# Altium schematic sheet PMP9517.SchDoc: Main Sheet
size 431 x 279 mm; Date: Not shown in title block; ApprovedBy: Not shown in title block; CheckedBy: Not shown in title block; Author: Not shown in title block; CompanyName: Not shown in title block; DrawnBy: Brian Gaynor; Engineer: Not shown in title block; Organization: Not shown in title block; Address1: Not shown in title block; Address2: Not shown in title block; Address3: Not shown in title block; Address4: Not shown in title block; DocumentNumber: 1; Revision: Use project parameter SCH_Rev; SheetNumber: 1; SheetTotal: 2; PageSetup: Record=PageOptions|CenterHorizontal=True|CenterVertical=True|PrintScale=0.66|XCorrection=1.00|YCorrection=1.00|PrintKind=0|BorderSize=5000000|LeftOffset=0|BottomOffset=0|Orientation=2|PaperLength=1000|PaperWidth=1000|Scale=100|PaperSource=15|PrintQuality=600|MediaType=1|DitherType=10|PaperKind=Letter|PrintScaleMode=1
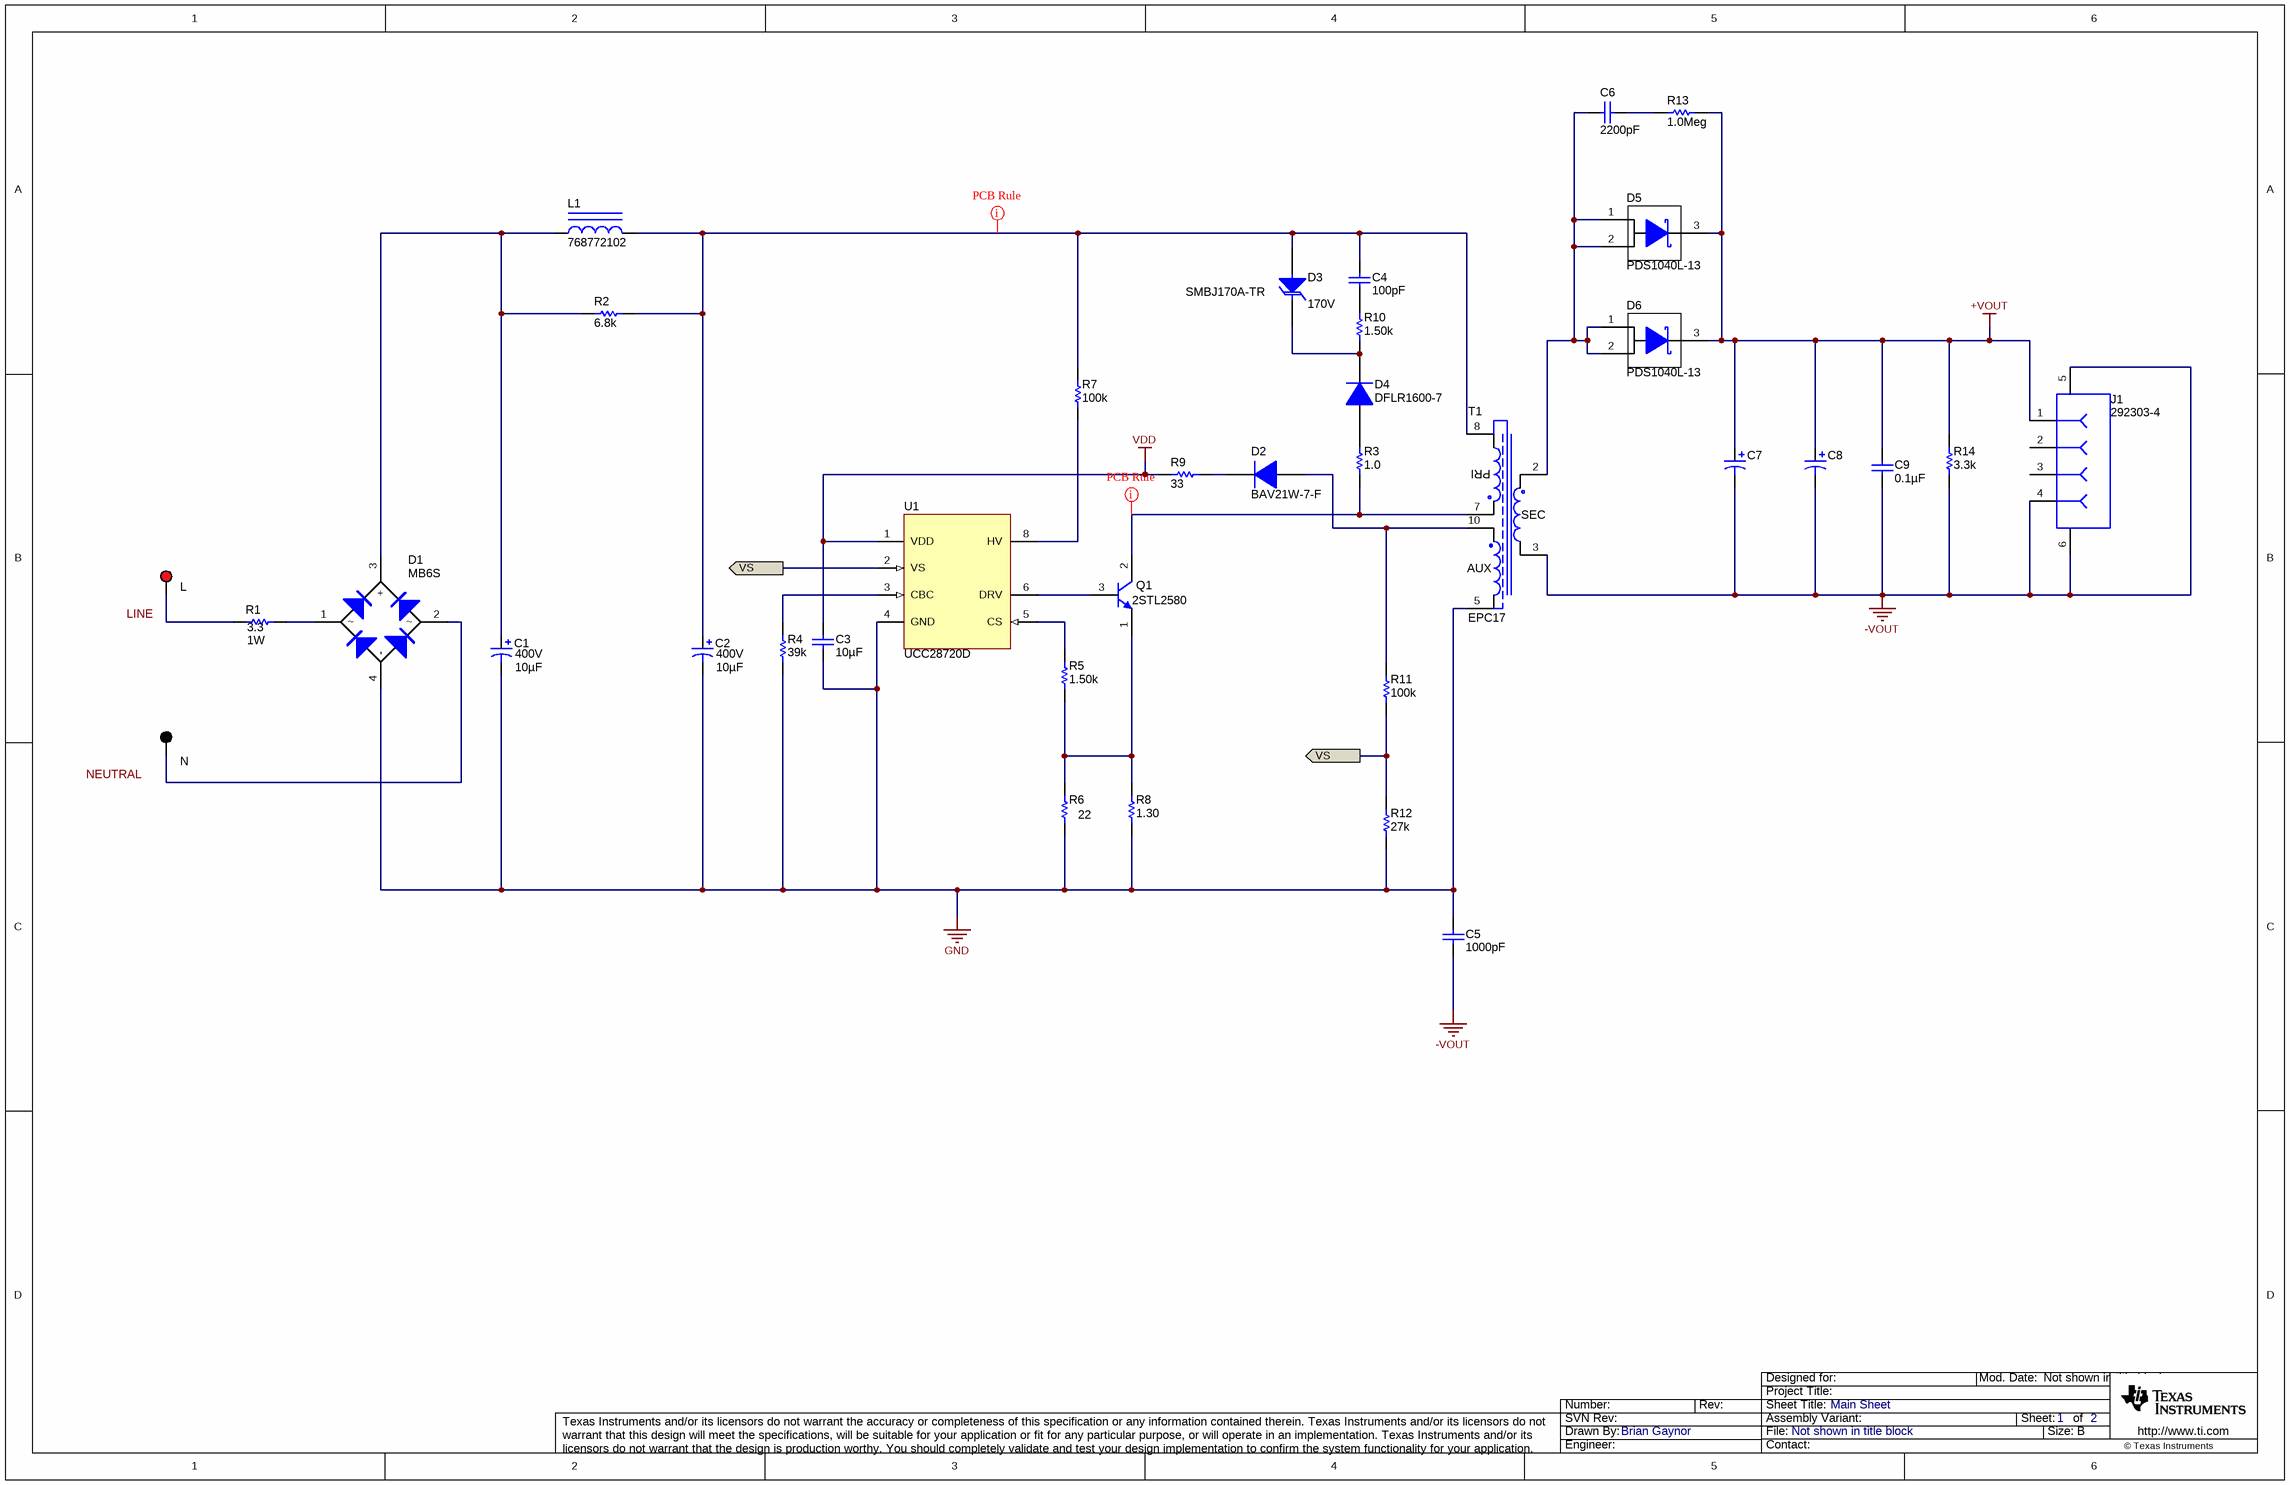
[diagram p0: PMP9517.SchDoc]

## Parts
C1  value 10µF  VDC_V: 400V  [CAPPRD500W60D1000H1250]  (hidden comment: UVC2G100MPD)
C2  value 10µF  VDC_V: 400V  [CAPPRD500W60D1000H1250]  (hidden comment: UVC2G100MPD)
C3  ValueDisplayed: 10µF  [1210]  (hidden comment: 1210YD106KAT2A)
C4  ValueDisplayed: 100pF  [1206]  (hidden comment: C1206C101JCGACTU)
C5  ValueDisplayed: 1000pF  [CAPRD750W60D750H1050]  (hidden comment: VY2102M29Y5UG63V7)
C6  ValueDisplayed: 2200pF  [0805_HV]  (hidden comment: 08055C222KAT2A)
C7  RNE0J122MDN1PX  [NRE-AX_800x1080]  (value not drawn)
C8  CAP ALUM 1200UF 6.3V 20% RADIAL  [NRE-AX_800x1080]  (value not drawn)
C9  ValueDisplayed: 0.1µF  [0805_HV]  (hidden comment: 08055C104JAT2A)
D1  MB6S  [MiniDIP-MB6S]
D2  BAV21W-7-F  [SOD-123]
D3  SMBJ170A-TR  value 170V  [SMB]
D4  DFLR1600-7  [powerDI123]
D5  PDS1040L-13  [powerdi5]
D6  PDS1040L-13  [powerdi5]
J1  292303-4  [CONN_TE_292303-4]
L  5005  [Keystone5005]  (value not drawn)
L1  768772102  [IND_WE-TI_8095]
N  5006  [Keystone5006]  (value not drawn)
Q1  2STL2580  [TO-92_AllBent]
R1  value 3.3  Power_W: 1W  [RES_ERG1S_V]  (hidden comment: SPP1UL3R30JLF)
R2  value 6.8k  [0805_HV]  (hidden comment: CRCW08056K80JNEA)
R3  value 1.0  [1206]  (hidden comment: CRCW12061R00JNEA)
R4  value 39k  [0603]  (hidden comment: CRCW060339K0JNEA)
R5  value 1.50k  [0603]  (hidden comment: CRCW06031K50FKEA)
R6  value 22  [2512M]  (hidden comment: CRCW251222R0JNEGHP)
R7  value 100k  [1206]  (hidden comment: RC1206FR-07100KL)
R8  value 1.30  [2512M]  (hidden comment: ERJ-1TRQF1R3U)
R9  value 33  [0603]  (hidden comment: CRCW060333R0JNEA)
R10  value 1.50k  [1206]  (hidden comment: CRCW12061K50FKEA)
R11  value 100k  [0603]  (hidden comment: CRCW0603100KFKEA)
R12  value 27k  [0603]  (hidden comment: RC0603JR-0727KL)
R13  value 1.0Meg  [0805_HV]  (hidden comment: CRCW08051M00JNEA)
R14  value 3.3k  [0805_HV]  (hidden comment: CRCW08053K30JNEA)
T1  EPC17  [MAG\TH\EPC17]
U1  UCC28720D  [D0007A_N]

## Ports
VS

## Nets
+VOUT: C7.1(+) C8.1(+) C9.2 D5.3(K) D6.3(K) J1.1 R13.2 R14.2
-VOUT: C5.2 C7.2(-) C8.2(-) C9.1 J1.4 J1.5 J1.6 R14.1 T1.3
GND: C1.2(-) C2.2(-) C3.2 C5.1 D1.4(-) R4.1 R6.1 R8.1 R12.1 T1.5 U1.4(GND)
VDD: C3.1 R9.1 U1.1(VDD)
VS: R11.1 R12.2 U1.2(VS) ; port VS
NetC1_1: C1.1(+) D1.3(+) L1.1 R2.1
NetC2_1: C2.1(+) C4.1 D3.2(A) L1.2 R2.2 R7.1 T1.8
NetC4_2: C4.2 R10.2
NetC6_1: C6.1 D5.1(A) D5.2(A) D6.1(A) D6.2(A) T1.2
NetC6_2: C6.2 R13.1
NetD1_1: D1.1 R1.2
NetD1_2: D1.2 N.1
NetD2_1: D2.1(K) R9.2
NetD2_2: D2.2(A) R11.2 T1.10
NetD3_1: D3.1(K) D4.1(K) R10.1
NetD4_2: D4.2(A) R3.2
NetL_1: L.1 R1.1
NetQ1_1: Q1.1(B) R5.1 R6.2 R8.2
NetQ1_2: Q1.2(C) R3.1 T1.7
NetQ1_3: Q1.3(E) U1.6(DRV)
NetR4_2: R4.2 U1.3(CBC)
NetR5_2: R5.2 U1.5(CS)
NetR7_2: R7.2 U1.8(HV)

Not connected (* = marked no-connect by the designer): J1 2 3

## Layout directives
rule Clearance Constraint [Clearance = 1mm]: NetC2_1, NetQ1_2

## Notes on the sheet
- Labels drawn without touching a wire or pin: LINE, NEUTRAL

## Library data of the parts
C1 C2 = Capacitor_Polarized: CAP, [Technology], xxxF, xxV, +/-xx%, xxOhm ESR, [MountType]; Manufacturer: Nichicon; Description: CAP ALUM 10UF 400V 20% RADIAL; Ripple Current: 100mA; Lifetime @ Temp.: 2000 Hrs @ 105°C; Tolerance_%: ±20%
C3 = 1210YD106KAT2A: CAP, CERM, 10uF, 16V, +/-10%, X5R, 1210; Manufacturer: AVX; Polarized: N; CompType: Capacitor; U/M: EA; Cap_F: 0.00001; Tolerance_%: 10; Value1: Unknown; VDC_V: 16; TaMin_C: -55; TaMax_C: 85
C4 = C1206C101JCGACTU: CAP, CERM, 100pF, 500V, +/-5%, C0G/NP0, 1206; Manufacturer: Kemet; Polarized: N; CompType: Capacitor; U/M: EA; Cap_F: 0.0000000001; Tolerance_%: 5; Value1: Unknown; VDC_V: 500; TaMin_C: -55; TaMax_C: 125
C5 = VY2102M29Y5UG63V7: CAP, CERM, 1000pF, 300V, +/-20%, Y5U, Radial Disc 7.5mm, ls=7.5; Manufacturer: Vishay-Bccomponents; Polarized: N; CompType: Capacitor; U/M: EA; Cap_F: 0.000000001; Tolerance_%: 20; Value1: Unknown; VDC_V: 300; TaMin_C: -40; TaMax_C: 125
C6 = 08055C222KAT2A: CAP, CERM, 2200pF, 50V, +/-10%, X7R, 0805; Manufacturer: AVX; Polarized: N; CompType: Capacitor; U/M: EA; Cap_F: 0.0000000022; Tolerance_%: 10; ESR_Ohm: 0.183; Value1: 0.183 ohm; VDC_V: 50; TaMin_C: -55; TaMax_C: 125; Cap_Case: 0805
C7 = Capacitor_Polarized: CAP, [Technology], xxxF, xxV, +/-xx%, xxOhm ESR, [MountType]; Manufacturer: Nichicon; Ripple Current: 5.7A; Tolerance_%: ±20%; Description: CAP ALUM 1200UF 6.3V 20% RADIAL; Type: Polymer; Lifetime @ Temp.: 2000 Hrs @ 105°C; Value: 1200µF; ESR_Ohm: 10 mOhm; VDC_V: 6.3V
C8 = Capacitor_Polarized: CAP, [Technology], xxxF, xxV, +/-xx%, xxOhm ESR, [MountType]; PartNumber: RNE0J122MDN1PX; Manufacturer: Nichicon; Ripple Current: 5.7A; Type: Polymer; Lifetime @ Temp.: 2000 Hrs @ 105°C; Value: 1200µF; ESR_Ohm: 10 mOhm
C9 = 08055C104JAT2A: CAP, CERM, 0.1uF, 50V, +/-5%, X7R, 0805; Manufacturer: AVX; Polarized: N; CompType: Capacitor; U/M: EA; Cap_F: 0.0000001; Tolerance_%: 5; ESR_Ohm: 0.024; Value1: 0.024 ohm; VDC_V: 50; TaMin_C: -55; TaMax_C: 125; Cap_Case: 0805
D1 = MB6S: Diode, Switching-Bridge, 600V, 1A, TH; U/M: EA; Io_A: 1
D2 = BAV21W-7-F: Diode, Switching, 200V, 0.2A, SOD-123; Manufacturer: Diodes Inc.; Value: 1.25V; U/M: EA; Vf_V: 1.25; Io_A: 0.2; Vr_V: 200; TJmax_C: 150
D3 = SMBJ170A-TR: Diode, TVS, Uni, 170V, 600W, SMB; Manufacturer: ST Microelectronics; U/M: EA; Power_W: 600; Vr_V: 170
D4 = Diode: Diode, [Type], xxxV, x.xxA, [PackageReference]; Manufacturer: Diodes Inc; Value: 1.1V @ 1A; Vr_V: 600V; Speed: Standard Recovery >500ns, > 200mA (Io); Thermal Resistance: 6°C/W Jl; Capacitance @ Vr, F: 10pF @ 4V, 1MHz; Io_A: 1A; Type: Standard; Current - Reverse Leakage @ Vr: 3µA @ 600V; Description: DIODE GP 600V 1A POWERDI123
D5 D6 = 30WQ04FNPBF: Diode, Schottky, 40V, 3.5A, DPAK; Manufacturer: Diodes Inc; Description: DIODE SCHOTTKY 40V 10A POWERDI5; Thermal Resistance: 1.5°C/W Jl; Current - Reverse Leakage @ Vr: 600µA @ 40V; Speed: Fast Recovery =< 500ns, > 200mA (Io); Value: 490mV @ 10A; Io_A: 10A
J1 = 292303-4: Connector, USB Type A, Receptacle, R/A, TH; Manufacturer: TE Connectivity; SymbolCreator: a0412235; U/M: EA
L = 5005: Test Point, Compact, Red, TH; Manufacturer: Keystone; CompType: Test Point Loop; U/M: EA
L1 = 768772102: Inductor, Shielded Drum Core, Metal Composite, 1mH, 0.5A, 1.7 ohm, TH; Manufacturer: Wurth Elektronik eiSos; DCR_ohm: 1.7; Ind_H: 1.0E-3; Imax_A: 0.5; Irms: 0.5A @ 40C rise; Isat: 0.55A @ 10% inductance drop; Value1: 1.7 ohm; U/M: EA
N = 5006: Test Point, Compact, Black, TH; Manufacturer: Keystone; CompType: Test Point Loop; U/M: EA
Q1 = STBV32-AP, ST Microelectronics: Transistor, NPN, 400V, 1.5A, TO-92AP; DC Collector/Base Gain hfe Min: 60 V; Maximum DC Collector Current: 2 A; Maximum Power Dissipation: 1.5 W; Product Status: New at Mouser; Emitter- Base Voltage VEBO: 9 V; Description: Transistors Bipolar - BJT High Volt NPN Trans 800V Vces 400V Vceo; Continuous Collector Current: 1 A
R1 = Resistor: RES, xxx ohm, x%, xW, [PackageReference]; Manufacturer: TT Electronics/IRC; Description: RES 3.3 OHM 1W 5% AXIAL; TempCo: ±300ppm/°C; Tolerance_%: ±5%
R2 = CRCW08056K80JNEA: RES, 6.8k ohm, 5%, 0.125W, 0805; Manufacturer: Vishay-Dale; CompType: Resistor; Res_ohm: 6800; Value_Code: 6k80; Tolerance_%: 5; Power_W: 0.125; VDC_V: 150; TempCo: 200 ppm/C; EIA_Code: E24; U/M: EA
R3 = CRCW12061R00JNEA: RES, 1.0 ohm, 5%, 0.25W, 1206; Manufacturer: Vishay-Dale; CompType: Resistor; Res_ohm: 1; Value_Code: 1R00; Tolerance_%: 5; Power_W: 0.25; VDC_V: 200; TempCo: 200 ppm/C; EIA_Code: E24; U/M: EA
R4 = CRCW060339K0JNEA: RES, 39k ohm, 5%, 0.1W, 0603; Manufacturer: Vishay-Dale; CompType: Resistor; Res_ohm: 39000; Value_Code: 39k0; Tolerance_%: 5; Power_W: 0.1; VDC_V: 75; TempCo: 200 ppm/C; EIA_Code: E24; U/M: EA
R5 = CRCW06031K50FKEA: RES, 1.50k ohm, 1%, 0.1W, 0603; Manufacturer: Vishay-Dale; CompType: Resistor; Res_ohm: 1500; Value_Code: 1k50; Tolerance_%: 1; Power_W: 0.1; VDC_V: 75; TempCo: 100 ppm/C; EIA_Code: E96; U/M: EA
R6 = CRCW251222R0JNEGHP: RES, 22 ohm, 5%, 1.5W, 2512; Manufacturer: Vishay-Dale; CompType: Resistor; Value_Code: 22R0; Tolerance_%: 5; Power_W: 1.5; VDC_V: 500; TempCo: 200 ppm/C; EIA_Code: E24; U/M: EA
R7 = RC1206FR-07100KL: RES, 100k ohm, 1%, 0.25W, 1206; Manufacturer: Yageo America; CompType: Resistor; Res_ohm: 100000; Tolerance_%: 1; Power_W: 0.25; VDC_V: 200; TempCo: 100 ppm/C; EIA_Code: E96; U/M: EA
R8 = ERJ-1TRQF1R3U: RES, 1.30 ohm, 1%, 1W, 2512; Manufacturer: Panasonic; CompType: Resistor; Res_ohm: 1.3; Value_Code: 1R30; Tolerance_%: 1; TempCo: 100 ppm/C; EIA_Code: E96; U/M: EA
R9 = CRCW060333R0JNEA: RES, 33 ohm, 5%, 0.1W, 0603; Manufacturer: Vishay-Dale; CompType: Resistor; Value_Code: 33R0; Tolerance_%: 5; Power_W: 0.1; VDC_V: 75; TempCo: 200 ppm/C; EIA_Code: E24; U/M: EA
R10 = CRCW12061K50FKEA: RES, 1.50k ohm, 1%, 0.25W, 1206; Manufacturer: Vishay-Dale; CompType: Resistor; Res_ohm: 1500; Value_Code: 1k50; Tolerance_%: 1; Power_W: 0.25; VDC_V: 200; TempCo: 100 ppm/C; EIA_Code: E96; U/M: EA
R11 = CRCW0603100KFKEA: RES, 100k ohm, 1%, 0.1W, 0603; Manufacturer: Vishay-Dale; CompType: Resistor; Res_ohm: 100000; Tolerance_%: 1; Power_W: 0.1; VDC_V: 75; TempCo: 100 ppm/C; EIA_Code: E96; U/M: EA
R12 = RC0603JR-0727KL: RES, 27k ohm, 5%, 0.1W, 0603; Manufacturer: Yageo America; CompType: Resistor; Res_ohm: 27000; Value_Code: 27k0; Tolerance_%: 5; Power_W: 0.1; VDC_V: 50; TempCo: 100 ppm/C; EIA_Code: E24; U/M: EA
R13 = CRCW08051M00JNEA: RES, 1.0Meg ohm, 5%, 0.125W, 0805; Manufacturer: Vishay-Dale; CompType: Resistor; Res_ohm: 1000000; Value_Code: 1M00; Tolerance_%: 5; Power_W: 0.125; VDC_V: 150; TempCo: 200 ppm/C; EIA_Code: E24; U/M: EA
R14 = CRCW08053K30JNEA: RES, 3.3k ohm, 5%, 0.125W, 0805; Manufacturer: Vishay-Dale; CompType: Resistor; Res_ohm: 3300; Value_Code: 3k30; Tolerance_%: 5; Power_W: 0.125; VDC_V: 150; TempCo: 200 ppm/C; EIA_Code: E24; U/M: EA
T1 = EPC17: JohnGriffin; CompType: Transformer; U/M: EA
U1 = UCC28720D: CONSTANT-VOLTAGE, CONSTANT-CURRENT CONTROLLER WITH PRIMARY SIDE REGULATION, D0007A; Alternate Manufacturer: None; Manufacturer: Texas Instruments; SymbolCreator: a0411947; CompType: IC; U/M: EA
